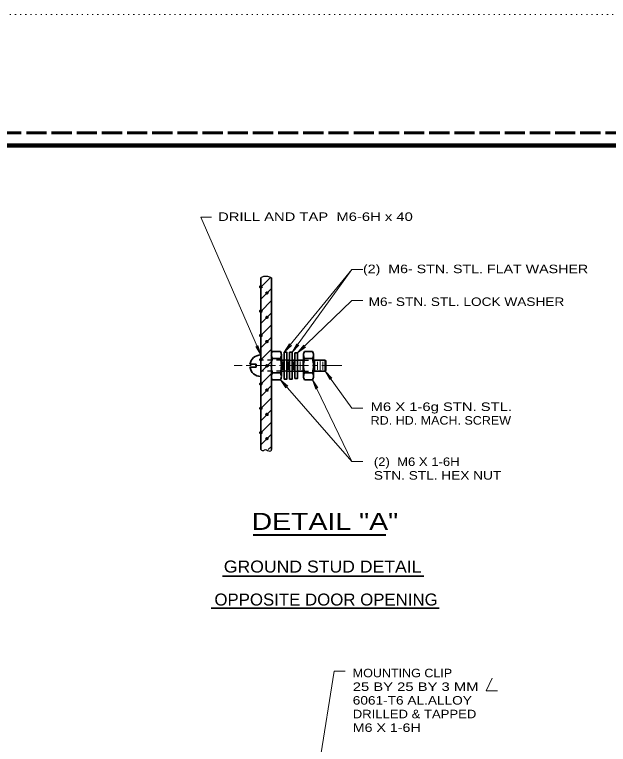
# Model space of a CAD drawing. Extents: x 312583 to 312854, y 144419 to 144597.
# Drawn here: x 312653.1 to 312706.2, y 144531.6 to 144596.8 of the extents above; entities that cross this region are included whole.
import ezdxf
from ezdxf.enums import TextEntityAlignment as Align

# ---------------------------------------------------------------- set-up
doc = ezdxf.new("R2010")
doc.units = 0
doc.header["$LTSCALE"] = 0.3
doc.header["$PDMODE"] = 32
doc.header["$PDSIZE"] = 0.15
for name, pattern in [('DOTTED', [1.5, 0.3, -1.2]), ('LONG_DASH_SHORT_DASH', [9.9, 6, -1.2, 1.5, -1.2]), ('LONG_DASHED', [7.5, 6, -1.5]), ('SHORT_DASHED', [2.7, 1.5, -1.2])]:
    doc.linetypes.add(name, pattern=pattern)
for name, color, linetype, lineweight in [('1', 7, 'Continuous', 40), ('2', 7, 'Continuous', 13), ('62', 7, 'DOTTED', 13), ('63', 7, 'LONG_DASHED', 60)]:
    doc.layers.add(name, color=color, linetype=linetype, lineweight=lineweight)

msp = doc.modelspace()

# ---------------------------------------------------------------- linework, layer by layer
at = {"layer": '1', "lineweight": 35}
for p, q in [((312675.1418, 144557.948), (312675.1418, 144573.2813)), ((312676.1001, 144557.948), (312676.1001, 144573.2813)), ((312676.1845, 144566.6957), (312676.9051, 144566.6957)), ((312679.0595, 144566.6957), (312679.7801, 144566.6957)), ((312676.0925, 144566.4197), (312676.0925, 144565.4383)), ((312676.1845, 144566.067), (312676.9051, 144566.067)), ((312676.9895, 144566.4197), (312676.9895, 144565.4383)), ((312677.0048, 144565.9137), (312677.2501, 144565.9137)), ((312677.4878, 144565.9137), (312677.7255, 144565.9137)), ((312677.9631, 144565.9137), (312678.2008, 144565.9137)), ((312678.4385, 144565.9137), (312678.9675, 144565.9137)), ((312678.9675, 144566.4197), (312678.9675, 144565.4383)), ((312679.0595, 144566.067), (312679.7801, 144566.067)), ((312679.8645, 144566.4197), (312679.8645, 144565.4383)), ((312679.8645, 144565.9137), (312680.8918, 144565.9137)), ((312680.8918, 144565.9137), (312680.8918, 144565.4383)), ((312674.1835, 144565.561), (312674.7431, 144565.561)), ((312674.1835, 144565.3157), (312674.7431, 144565.3157)), ((312674.7431, 144565.561), (312674.7431, 144565.3157)), ((312676.0925, 144564.457), (312676.0925, 144565.4383)), ((312676.9895, 144564.457), (312676.9895, 144565.4383)), ((312678.9675, 144564.457), (312678.9675, 144565.4383)), ((312679.8645, 144564.457), (312679.8645, 144565.4383)), ((312680.8918, 144564.9553), (312680.8918, 144565.4383)), ((312676.1845, 144564.8097), (312676.9051, 144564.8097)), ((312677.0048, 144564.9553), (312677.2501, 144564.9553)), ((312677.4878, 144564.9553), (312677.7255, 144564.9553)), ((312677.9631, 144564.9553), (312678.2008, 144564.9553)), ((312678.4385, 144564.9553), (312678.9675, 144564.9553)), ((312679.0595, 144564.8097), (312679.7801, 144564.8097)), ((312679.8645, 144564.9553), (312680.8918, 144564.9553)), ((312676.1845, 144564.181), (312676.9051, 144564.181)), ((312679.0595, 144564.181), (312679.7801, 144564.181))]:
    msp.add_line(p, q, dxfattribs=at)
at = {"layer": '1', "lineweight": 13}
for p, q in [((312675.1418, 144572.4533), (312675.9775, 144573.2813)), ((312675.1418, 144571.3647), (312676.1001, 144572.323)), ((312675.1418, 144570.2837), (312676.1001, 144571.242)), ((312675.1418, 144569.195), (312676.1001, 144570.1533)), ((312675.1341, 144568.114), (312676.1001, 144569.0723)), ((312675.1418, 144567.0253), (312676.1001, 144567.9913)), ((312675.1418, 144565.9443), (312676.1001, 144566.9027)), ((312678.9138, 144565.9213), (312678.9138, 144565.4383)), ((312679.9795, 144565.9213), (312679.9795, 144565.4383)), ((312680.4548, 144565.9213), (312680.4548, 144565.4383)), ((312675.1418, 144564.8633), (312676.1001, 144565.8217)), ((312677.1275, 144565.7987), (312677.1275, 144565.4383)), ((312677.1275, 144565.078), (312677.1275, 144565.4383)), ((312677.6028, 144565.7987), (312677.6028, 144565.4383)), ((312677.6028, 144565.078), (312677.6028, 144565.7987)), ((312677.6028, 144565.078), (312677.6028, 144565.4383)), ((312678.0858, 144565.078), (312678.0858, 144565.7987)), ((312678.6761, 144565.7987), (312678.6761, 144565.4383)), ((312678.6761, 144565.078), (312678.6761, 144565.4383)), ((312678.9138, 144564.9553), (312678.9138, 144565.4383)), ((312679.9795, 144564.9553), (312679.9795, 144565.4383)), ((312680.2171, 144565.791), (312680.2171, 144565.4383)), ((312680.2171, 144565.0703), (312680.2171, 144565.4383)), ((312680.4548, 144564.9553), (312680.4548, 144565.4383)), ((312680.6925, 144565.791), (312680.6925, 144565.4383)), ((312680.6925, 144565.0703), (312680.6925, 144565.4383)), ((312675.1418, 144563.7747), (312676.1001, 144564.733)), ((312675.1418, 144562.6937), (312676.1001, 144563.652)), ((312675.1418, 144561.605), (312676.1001, 144562.571)), ((312675.1418, 144560.524), (312676.1001, 144561.4823)), ((312675.1418, 144559.443), (312676.1001, 144560.4013)), ((312675.1418, 144558.3543), (312676.1001, 144559.3127)), ((312675.8165, 144557.948), (312676.1001, 144558.2317))]:
    msp.add_line(p, q, dxfattribs=at)
at = {"layer": '1', "linetype": 'SHORT_DASHED', "lineweight": 25}
for p, q in [((312677.0048, 144565.9137), (312675.1418, 144565.9137)), ((312677.4878, 144565.9137), (312677.2501, 144565.9137)), ((312677.7255, 144565.9137), (312677.9631, 144565.9137)), ((312678.2008, 144565.9137), (312678.4385, 144565.9137)), ((312678.9675, 144565.9137), (312679.8645, 144565.9137)), ((312677.0048, 144564.9553), (312675.1418, 144564.9553)), ((312677.4878, 144564.9553), (312677.2501, 144564.9553)), ((312677.7255, 144564.9553), (312677.9631, 144564.9553)), ((312678.2008, 144564.9553), (312678.4385, 144564.9553)), ((312678.9675, 144564.9553), (312679.8645, 144564.9553))]:
    msp.add_line(p, q, dxfattribs=at)
at = {"layer": '1', "linetype": 'LONG_DASH_SHORT_DASH', "lineweight": 13}
msp.add_line((312682.3945, 144565.4383), (312672.7651, 144565.4383), dxfattribs=at)
at = {"layer": '1', "lineweight": 158}
msp.add_lwpolyline([(312616.5, 144423.1446), (312616.5, 144585.0846), (312849, 144585.0846)], dxfattribs=at)
at = {"layer": '1', "lineweight": 35}
for points in [[(312677.2501, 144564.2423), (312677.4878, 144564.2423), (312677.4878, 144566.6343), (312677.2501, 144566.6343)], [(312677.7255, 144564.2423), (312677.9631, 144564.2423), (312677.9631, 144566.6343), (312677.7255, 144566.6343)], [(312678.2008, 144564.3037), (312678.4385, 144564.3037), (312678.4385, 144566.573), (312678.2008, 144566.573)]]:
    msp.add_lwpolyline(points, close=True, dxfattribs=at)
for points in [[(312680.8918, 144565.9137), (312680.9761, 144565.8523), (312680.9761, 144565.4383)], [(312680.8918, 144564.9553), (312680.9761, 144565.0167), (312680.9761, 144565.4383)]]:
    msp.add_lwpolyline(points, dxfattribs=at)
at = {"layer": '1', "lineweight": 13}
msp.add_lwpolyline([(312695.8272, 144537.5374), (312695.2752, 144536.4028), (312696.3102, 144536.4028)], dxfattribs=at)
at = {"layer": '1', "lineweight": 35}
for centre, radius, start, end in [((312676.6115, 144566.4017), 0.5187, 145.8703, 178.33743), ((312676.4685, 144566.4017), 0.5187, 1.66257, 34.1297), ((312679.4865, 144566.4017), 0.5187, 145.8703, 178.33743), ((312679.3435, 144566.4017), 0.5187, 1.66257, 34.1297), ((312675.1355, 144565.4345), 0.9583, 89.85149, 172.64599), ((312677.5457, 144566.6522), 1.4854, 191.77014, 203.36365), ((312678.7714, 144565.3692), 2.6807, 164.99798, 178.595), ((312675.5343, 144566.6522), 1.4854, 336.63635, 348.22986), ((312674.3086, 144565.3692), 2.6807, 1.405, 15.00202), ((312680.4207, 144566.6522), 1.4854, 191.77014, 203.36365), ((312681.6464, 144565.3692), 2.6807, 164.99798, 178.595), ((312678.4093, 144566.6522), 1.4854, 336.63635, 348.22986), ((312677.1836, 144565.3692), 2.6807, 1.405, 15.00202), ((312675.1355, 144565.4345), 0.9583, 187.12299, 270.14851), ((312678.7714, 144565.5007), 2.6807, 181.405, 195.00202), ((312674.3086, 144565.5007), 2.6807, 344.99798, 358.595), ((312681.6464, 144565.5007), 2.6807, 181.405, 195.00202), ((312677.1836, 144565.5007), 2.6807, 344.99798, 358.595), ((312677.5457, 144564.2177), 1.4854, 156.63635, 168.22986), ((312675.5343, 144564.2177), 1.4854, 11.77014, 23.36365), ((312680.4207, 144564.2177), 1.4854, 156.63635, 168.22986), ((312678.4093, 144564.2177), 1.4854, 11.77014, 23.36365), ((312676.6115, 144564.4682), 0.5187, 181.66257, 214.1297), ((312676.4685, 144564.4682), 0.5187, 325.8703, 358.33743), ((312679.4865, 144564.4682), 0.5187, 181.66257, 214.1297), ((312679.3435, 144564.4682), 0.5187, 325.8703, 358.33743)]:
    msp.add_arc(centre, radius, start, end, dxfattribs=at)
at = {"layer": '1', "lineweight": 25}
for points in [[(312675.1418, 144573.2813), (312675.2951, 144573.381), (312675.5635, 144573.4347), (312675.7398, 144573.4347), (312676.1001, 144573.2813)], [(312675.1418, 144557.948), (312675.4178, 144557.8637), (312675.5635, 144557.9557), (312675.7628, 144557.8637), (312676.0848, 144557.8637), (312676.1001, 144557.948)]]:
    msp.add_spline(points, degree=3, dxfattribs=at)
at = {"layer": '1'}
for p in [(312675.1571, 144572.4687), (312675.7015, 144571.9243), (312675.1571, 144570.299), (312675.7015, 144569.7547), (312675.1571, 144568.1293), (312675.7015, 144567.5927), (312675.1571, 144565.9673), (312675.7015, 144565.423), (312675.1571, 144563.7977), (312675.7015, 144563.2533), (312675.1571, 144561.628), (312675.7015, 144561.0837), (312675.1571, 144559.4583), (312675.7015, 144558.914)]:
    msp.add_point(p, dxfattribs=at)
at = {"layer": '2'}
for p, q in [((312669.7905, 144578.694), (312675.1418, 144566.3967)), ((312669.7905, 144578.694), (312670.7488, 144578.694)), ((312683.2991, 144574.0173), (312677.2501, 144566.6343)), ((312683.2991, 144574.0173), (312677.9631, 144566.6343)), ((312683.2991, 144574.0173), (312684.2575, 144574.0173)), ((312683.2991, 144571.2497), (312678.4385, 144566.573)), ((312683.2991, 144571.2497), (312684.2575, 144571.2497)), ((312674.8965, 144567.2323), (312674.9041, 144566.9333)), ((312675.1418, 144566.3967), (312674.8965, 144567.2323)), ((312677.2501, 144566.6343), (312677.7178, 144567.378)), ((312677.2501, 144566.6343), (312677.8865, 144567.24)), ((312677.7178, 144567.378), (312677.6258, 144567.0943)), ((312677.8865, 144567.24), (312677.6258, 144567.0943)), ((312677.9631, 144566.6343), (312678.3848, 144567.401)), ((312677.9631, 144566.6343), (312678.5611, 144567.2783)), ((312678.3848, 144567.401), (312678.3081, 144567.1173)), ((312678.5611, 144567.2783), (312678.3081, 144567.1173)), ((312678.4385, 144566.573), (312678.9905, 144567.2553)), ((312678.9905, 144567.2553), (312678.8678, 144566.987)), ((312674.6971, 144567.148), (312674.9041, 144566.9333)), ((312675.1418, 144566.3967), (312674.6971, 144567.148)), ((312678.4385, 144566.573), (312679.1361, 144567.0943)), ((312679.1361, 144567.0943), (312678.8678, 144566.987)), ((312683.2991, 144561.6433), (312680.8918, 144564.9553)), ((312680.8918, 144564.9553), (312681.3135, 144564.1963)), ((312680.8918, 144564.9553), (312681.4898, 144564.319)), ((312683.2991, 144556.8823), (312676.9051, 144564.181)), ((312676.9051, 144564.181), (312677.3958, 144563.4603)), ((312676.9051, 144564.181), (312677.5568, 144563.5983)), ((312683.2991, 144556.8823), (312679.7801, 144564.181)), ((312679.7801, 144564.181), (312680.0561, 144563.353)), ((312679.7801, 144564.181), (312680.2478, 144563.445)), ((312681.3135, 144564.1963), (312681.2445, 144564.48)), ((312681.4898, 144564.319), (312681.2445, 144564.48)), ((312677.3958, 144563.4603), (312677.2961, 144563.7363)), ((312677.5568, 144563.5983), (312677.2961, 144563.7363)), ((312680.0561, 144563.353), (312680.0331, 144563.6443)), ((312680.2478, 144563.445), (312680.0331, 144563.6443)), ((312683.2991, 144561.6433), (312684.2575, 144561.6433)), ((312683.2991, 144556.8823), (312684.2575, 144556.8823)), ((312679.8185, 144526.415), (312681.7198, 144538.1603)), ((312681.7198, 144538.1603), (312682.6781, 144538.1603))]:
    msp.add_line(p, q, dxfattribs=at)
at = {"layer": '2', "lineweight": 40}
msp.add_line((312674.4787, 144550.3273), (312686.3136, 144550.3273), dxfattribs=at)
at = {"layer": '2', "lineweight": 35}
for p, q in [((312671.7207, 144546.6473), (312689.7085, 144546.6473)), ((312670.7286, 144543.7723), (312691.0961, 144543.7723))]:
    msp.add_line(p, q, dxfattribs=at)
at = {"layer": '62'}
msp.add_line((312601.2, 144596.7846), (312853.5, 144596.7846), dxfattribs=at)
at = {"layer": '63'}
msp.add_line((312851.75, 144586.2246), (312583.526, 144586.2246), dxfattribs=at)

# ---------------------------------------------------------------- texts
at = {"layer": '2'}
for s, width, p in [('DRILL AND TAP  M6-6H x 40', 1.3, (312671.3334, 144578.3596)), (' (2)  M6- STN. STL. FLAT WASHER', 1.25, (312683.9278, 144573.6963)), ('M6- STN. STL. LOCK WASHER', 1.2, (312684.7846, 144570.7676)), ('M6 X 1-6g STN. STL.', 1.3, (312684.9649, 144561.3914)), ('RD. HD. MACH. SCREW', 1.1, (312684.9649, 144560.1714)), ('(2)  M6 X 1-6H', 1.15, (312685.2525, 144556.4808)), ('STN. STL. HEX NUT', 1.2, (312685.2525, 144555.2608)), ('MOUNTING CLIP', 1.1, (312683.3679, 144537.6131)), ('25 BY 25 BY 3 MM', 1.3, (312683.3679, 144536.3931)), ('6061-T6 AL.ALLOY', 1.2, (312683.3679, 144535.1731)), ('DRILLED & TAPPED', 1.15, (312683.3679, 144533.9531)), ('M6 X 1-6H', 1.25, (312683.3679, 144532.7331))]:
    msp.add_text(s, height=0.76, dxfattribs=dict(at, width=width)).set_placement(p)
for s, height, width, p in [('DETAIL "A"', 1.52, 1.25, (312680.8794, 144550.774)), ('GROUND STUD DETAIL', 1.07, 1.1, (312680.6764, 144546.9652)), ('OPPOSITE DOOR OPENING', 1.07, 1.05, (312680.9813, 144544.0192))]:
    msp.add_text(s, height=height, dxfattribs=dict(at, width=width)).set_placement(p, align=Align.CENTER)

doc.saveas('drawing.dxf')
